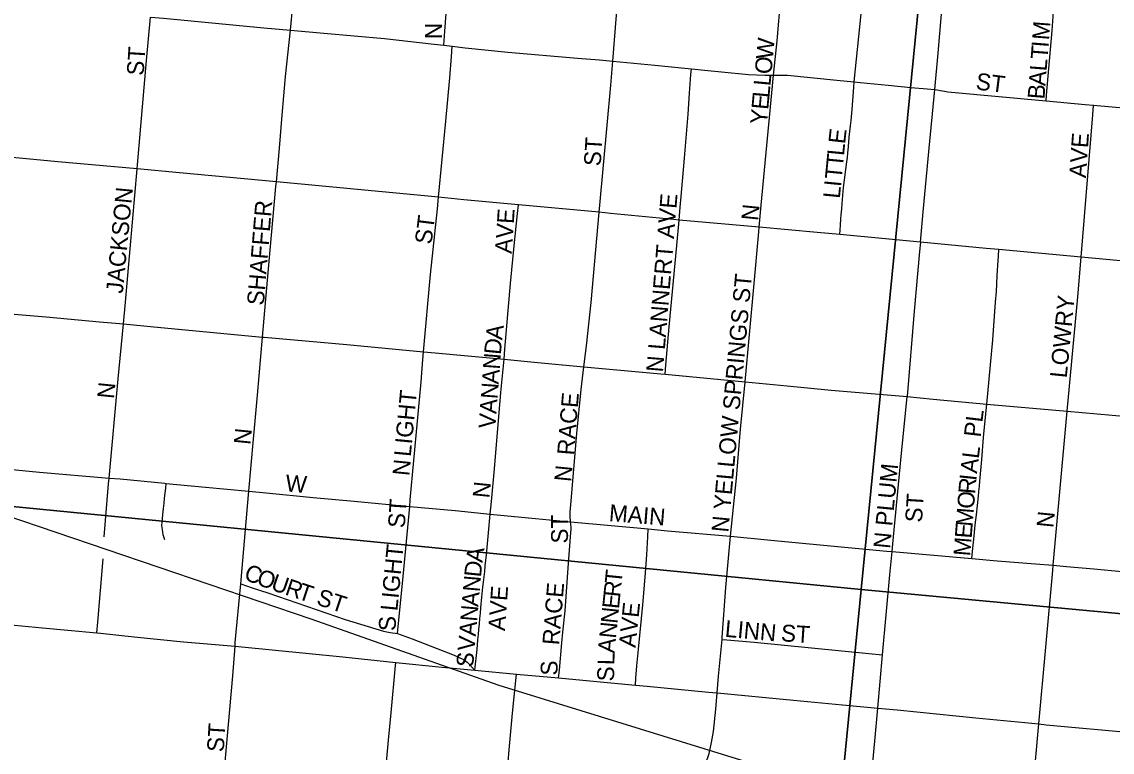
# Model space of a CAD drawing. Extents: x 1410790 to 1770854, y 566777 to 831614.
# Drawn here: x 1596372 to 1599605, y 703249 to 705415 of the extents above; entities that cross this region are included whole.
import ezdxf

# ---------------------------------------------------------------- set-up
doc = ezdxf.new("R2010")
doc.units = 0
for name, color, linetype in [('GM_X_City_Street', 7, 'Continuous'), ('GM_X_City_Street_Text', 7, 'Continuous'), ('GM_X_Rail_Line', 7, 'Continuous'), ('GM_X_Section', 7, 'Continuous'), ('GM_X_State_Route', 7, 'Continuous'), ('GM_X_US_Route', 7, 'Continuous')]:
    doc.layers.add(name, color=color, linetype=linetype)

msp = doc.modelspace()

# ---------------------------------------------------------------- linework, layer by layer
at = {"layer": 'GM_X_City_Street'}
for points in [[(1598840.1, 705236.8), (1598861, 705439.4), (1598863.5, 705471.4), (1598867.3, 705540.5), (1598872.1, 705604.7), (1598876, 705636.3), (1598878.7, 705664.4), (1598881, 705685.4), (1598881.8, 705699.3), (1598883.1, 705713.8), (1598883.9, 705728.3), (1598887.4, 705769.7), (1598888.7, 705785.2), (1598890.9, 705809.2)], [(1597168.5, 705390.7), (1597175.9, 705464.1), (1597191.7, 705627), (1597202.2, 705736.3)], [(1597623.6, 705345.8), (1597626.8, 705388), (1597647.5, 705663.5)], [(1598124, 705298.3), (1598134.4, 705423.1), (1598152.3, 705617.1)], [(1599409.2, 705180.5), (1599410.7, 705197.9), (1599417.4, 705277.1), (1599426.8, 705389.2), (1599431.3, 705445), (1599442.4, 705579.9), (1599445.7, 705614.4)], [(1598601.1, 705257), (1598611.3, 705359.2), (1598623, 705488.1), (1598631.2, 705571.8)], [(1596714.1, 704978.9), (1596715.1, 704991.2), (1596742.3, 705300.6), (1596753.5, 705429.3)], [(1596753.5, 705429.3), (1596792.1, 705425.8), (1597089.8, 705397.8), (1597168.5, 705390.7)], [(1597126.9, 704940.3), (1597135.7, 705040.9), (1597143.9, 705138.8), (1597154, 705252.7), (1597168.5, 705390.7)], [(1597168.5, 705390.7), (1597267.3, 705381.7), (1597447.5, 705365.9), (1597594.8, 705349.3), (1597623.6, 705345.8)], [(1597607.7, 704894.9), (1597628.9, 705120.2), (1597640.9, 705249.4), (1597645.7, 705312.7), (1597648.1, 705342.8)], [(1597623.6, 705345.8), (1597648.1, 705342.8)], [(1597648.1, 705342.8), (1597686.5, 705338.1), (1597812.9, 705325.3), (1598020.1, 705307.9), (1598085.1, 705302.1), (1598124, 705298.3)], [(1598084, 704850.4), (1598085.9, 704871.2), (1598118.1, 705227.6), (1598124, 705298.3)], [(1598124, 705298.3), (1598248.8, 705286.5), (1598357.4, 705275.4)], [(1598320.9, 704827.3), (1598324.1, 704865.1), (1598327.2, 704897.2), (1598336.7, 705010.4), (1598347.5, 705141), (1598351.7, 705203.5), (1598355.8, 705258.7), (1598357.4, 705275.4)], [(1598357.4, 705275.4), (1598396.1, 705271.5), (1598446.4, 705266.8), (1598527.1, 705259.5), (1598575.1, 705256.6), (1598601.1, 705257)], [(1598558.3, 704806), (1598564.5, 704871), (1598588.9, 705131.2), (1598601.1, 705257)], [(1598601.1, 705257), (1598626.2, 705257.4), (1598642.6, 705256.6), (1598789.1, 705242.1), (1598840.1, 705236.8)], [(1598797.2, 704784.5), (1598799.2, 704811.7), (1598800.6, 704830.8), (1598801.3, 704842.9), (1598803.2, 704860.8), (1598804.2, 704876.3), (1598808.8, 704923.8), (1598818.3, 704999.9), (1598820.1, 705012.9), (1598821.4, 705026.9), (1598823, 705044), (1598825.6, 705073.1), (1598827, 705090.2), (1598829.1, 705107.2), (1598831.2, 705122.1), (1598833.6, 705155.1), (1598838.9, 705221.1), (1598840.1, 705236.8)], [(1598840.1, 705236.8), (1598858.2, 705235.2), (1598940.8, 705227), (1599008.4, 705220.9), (1599056.3, 705216.6), (1599078.7, 705214.6)], [(1599078.7, 705214.6), (1599108, 705209.2), (1599117.6, 705207.7), (1599128.5, 705206.5), (1599409.2, 705180.5)], [(1599409.2, 705180.5), (1599524.7, 705169.8), (1599549.9, 705167.6)], [(1599512.8, 704717), (1599547.6, 705139.2), (1599549.9, 705167.6)], [(1599549.9, 705167.6), (1599704.4, 705154.1), (1599819.7, 705145), (1599846.7, 705142.8)], [(1596673.8, 704519), (1596679.8, 704584.1), (1596714.1, 704978.9)], [(1597086, 704480), (1597104, 704682.5), (1597125.7, 704927), (1597126.9, 704940.3)], [(1597563.5, 704436.9), (1597583.8, 704665.8), (1597604.5, 704860.9), (1597607.7, 704894.9)], [(1597801.8, 704414.4), (1597804.5, 704444.3), (1597820.9, 704638.7), (1597831.6, 704751.1), (1597841.7, 704846.4), (1597844.4, 704872.6)], [(1598038.8, 704392.3), (1598046.4, 704454.5), (1598060.3, 704582.9), (1598084, 704850.4)], [(1598279.7, 704370.1), (1598281.9, 704396.9), (1598287.4, 704464.6), (1598291.6, 704510.1), (1598313.9, 704751.9), (1598320.9, 704827.3)], [(1598516.6, 704347.3), (1598542.8, 704627.9), (1598557.1, 704792.4), (1598558.3, 704806)], [(1599233.2, 704281.6), (1599250.9, 704471.6), (1599259.1, 704583.4), (1599261.8, 704615.1), (1599264.3, 704662), (1599264.8, 704678.6), (1599265.6, 704692.8), (1599267.7, 704721.6), (1599269.1, 704739.7)], [(1599471.9, 704260.5), (1599503.2, 704599.4), (1599512.8, 704717)], [(1596630.9, 704062), (1596658.2, 704356.3), (1596673.8, 704519)], [(1597045.4, 704023.2), (1597059.5, 704177.5), (1597070.6, 704307.9), (1597086, 704480)], [(1597522.2, 703977.9), (1597524, 703997.8), (1597555.9, 704347.2), (1597561.5, 704413.3), (1597563.5, 704436.9)], [(1597760.9, 703955.2), (1597764.4, 703992.2), (1597773.7, 704089.4), (1597792.7, 704315.5), (1597801.8, 704414.4)], [(1597999, 703932.4), (1597997.9, 703949), (1597998, 703955.1), (1597998.2, 703961.6), (1598000.1, 703982.4), (1598018, 704194.4), (1598030.1, 704324.6), (1598038.8, 704392.3)], [(1598473.6, 703890.1), (1598490.7, 704061.4), (1598503.4, 704207.2), (1598516.6, 704347.3)], [(1598953, 703843.7), (1598955.1, 703867.1), (1598978.1, 704115.2), (1598997.3, 704303.6)], [(1599188.6, 703823.4), (1599190.7, 703844.2), (1599195.6, 703890.6), (1599198.8, 703923), (1599202.3, 703953.1), (1599208.2, 704008), (1599209.8, 704022.5), (1599211.5, 704037.6), (1599213, 704053.2), (1599218.3, 704117.3), (1599223.8, 704182.3), (1599231.3, 704262.3), (1599233.2, 704281.6)], [(1599430.2, 703803.4), (1599432.5, 703836.2), (1599471.9, 704260.5)], [(1596210.6, 704098.2), (1596312.7, 704090), (1596425, 704079.5), (1596630.9, 704062)], [(1596616.7, 703887.8), (1596629.4, 704044.9), (1596630.9, 704062)], [(1596630.9, 704062), (1596663.9, 704059.3), (1596796, 704046.7), (1596800.1, 704046.3)], [(1596796.7, 703878.4), (1596791.6, 703893.4), (1596788.8, 703909), (1596787.8, 703921), (1596789.1, 703940.8), (1596790.5, 703953.6), (1596792.6, 703971.4), (1596794, 703987.3), (1596795.7, 704001.9), (1596797.5, 704016.9), (1596798.8, 704032.5), (1596800.1, 704046.3)], [(1596800.1, 704046.3), (1596916.9, 704035.1), (1597045.4, 704023.2)], [(1597021.1, 703748.2), (1597030.4, 703851.6), (1597044.4, 704012.1), (1597045.4, 704023.2)], [(1597045.4, 704023.2), (1597096.5, 704018.3), (1597236, 704004.8), (1597357.9, 703993.2), (1597522.2, 703977.9)], [(1597486.5, 703600.7), (1597503.2, 703770), (1597522.2, 703977.9)], [(1597522.2, 703977.9), (1597657, 703965.3), (1597760.9, 703955.2)], [(1597715.5, 703492.1), (1597722, 703553.5), (1597724.7, 703581.8), (1597725.9, 703598.2), (1597727.4, 703613.1), (1597728.7, 703629.8), (1597730.2, 703645.3), (1597731.7, 703661.1), (1597732.9, 703676.9), (1597735.6, 703708.8), (1597739, 703738), (1597740.8, 703752.9), (1597742.5, 703769.3), (1597744.5, 703785.3), (1597746.4, 703801.5), (1597749.8, 703834.1), (1597755.8, 703899.6), (1597760.9, 703955.2)], [(1597760.9, 703955.2), (1597874.7, 703944.1), (1597957.4, 703936), (1597999, 703932.4)], [(1597963.8, 703469.4), (1597965.9, 703492.5), (1597973.3, 703572.8), (1597976.4, 703604.9), (1597982.8, 703668.4), (1597992.4, 703796), (1598000.3, 703900.7), (1598001, 703909.4), (1598000.6, 703916.1), (1597999, 703932.4)], [(1597999, 703932.4), (1598229.5, 703911.1)], [(1598191.3, 703448), (1598193, 703468.5), (1598196, 703505.4), (1598200.8, 703554), (1598213.8, 703686), (1598220.3, 703768), (1598225.1, 703834.4), (1598228.1, 703887.4), (1598229.5, 703911.1)], [(1598229.5, 703911.1), (1598286.9, 703905.7), (1598473.6, 703890.1)], [(1598448.4, 703583.4), (1598448.9, 703588.8), (1598459.3, 703737.1), (1598473.6, 703890.1)], [(1598473.6, 703890.1), (1598593, 703877.7), (1598936.4, 703845.1), (1598953, 703843.7)], [(1598924.3, 703538), (1598945.4, 703774.8), (1598953, 703843.7)], [(1598953, 703843.7), (1599188.6, 703823.4)], [(1596594.2, 703602.8), (1596597.2, 703634.1), (1596605.2, 703728.2), (1596613, 703822.5)], [(1599188.6, 703823.4), (1599263.5, 703816.9), (1599378.1, 703808), (1599430.2, 703803.4)], [(1599387.8, 703332.6), (1599428.9, 703788.3), (1599430.2, 703803.4)], [(1599430.2, 703803.4), (1599469.7, 703799.9), (1599550.6, 703792.8), (1599634.7, 703785.3), (1599865.4, 703763.4), (1599909.1, 703759.1)], [(1597004.4, 703563.1), (1597005.2, 703573.9), (1597021.1, 703748.2)], [(1597021.1, 703748.2), (1597055.1, 703736.8), (1597101.2, 703721.7), (1597330.6, 703642.9), (1597444.8, 703608.1), (1597464.6, 703604.2), (1597486.5, 703600.7)], [(1596170.1, 703643.6), (1596252.4, 703635.1), (1596350.8, 703625.8), (1596433.1, 703618), (1596508.7, 703610.9), (1596594.2, 703602.8)], [(1596594.2, 703602.8), (1596605.9, 703601.7), (1596705, 703591.1), (1596851.9, 703576.7), (1597004.4, 703563.1)], [(1597486.5, 703600.7), (1597529.2, 703585), (1597654.2, 703536.6), (1597666.6, 703531), (1597681.6, 703523.5), (1597692.9, 703515.8), (1597715.5, 703492.1)], [(1598434, 703424.9), (1598438.2, 703474.5), (1598448.4, 703583.4)], [(1598448.4, 703583.4), (1598462.6, 703582.2), (1598543.3, 703575), (1598883.8, 703542), (1598924.3, 703538)], [(1596924.6, 702672.4), (1596933.8, 702773.6), (1596948.9, 702936.9), (1596961.9, 703067.4), (1596976, 703230.8), (1596997.6, 703475.8), (1597004.4, 703563.1)], [(1597004.4, 703563.1), (1597014.9, 703562.3), (1597324.3, 703531.4), (1597481.3, 703515.2)], [(1598910.4, 703379.6), (1598924.3, 703538)], [(1597397, 702623.1), (1597401.2, 702670), (1597426.9, 702928.9), (1597432.1, 702992.8), (1597433.4, 703008.8), (1597439.4, 703073.6), (1597447.5, 703154.7), (1597459.4, 703284.4), (1597466.9, 703365.5), (1597480.4, 703506.1), (1597481.3, 703515.2)], [(1597481.3, 703515.2), (1597618.3, 703501), (1597715.5, 703492.1)], [(1597715.5, 703492.1), (1597839.2, 703480.8)], [(1597745.2, 702587.2), (1597748.3, 702598.6), (1597752.4, 702610.8), (1597755.9, 702619.6), (1597760.4, 702632.3), (1597763.4, 702647.8), (1597769.2, 702696.5), (1597772, 702729), (1597792.1, 702956.9), (1597797.4, 703022.2), (1597807.9, 703152.4), (1597817.7, 703266.9), (1597827.4, 703365), (1597837.3, 703461.5), (1597839.2, 703480.8)], [(1597839.2, 703480.8), (1597963.8, 703469.4)], [(1597963.8, 703469.4), (1597994.5, 703466.6), (1598191.3, 703448)], [(1598191.3, 703448), (1598226.6, 703444.6), (1598408, 703427.3), (1598434, 703424.9)], [(1598344.5, 703083.5), (1598348.7, 703092.5), (1598367.5, 703137.9), (1598399.2, 703213.7), (1598410, 703245.2), (1598417.5, 703277.7), (1598422.6, 703310.5), (1598429.9, 703376.1), (1598434, 703424.9)], [(1598434, 703424.9), (1598659.7, 703403.6), (1598805.5, 703389.8), (1598910.4, 703379.6)], [(1598877, 703034.8), (1598878, 703044.8), (1598891.5, 703174), (1598909.5, 703369), (1598910.4, 703379.6)], [(1598910.4, 703379.6), (1598967, 703374.3), (1599200.6, 703351.1), (1599387.8, 703332.6)], [(1599322.5, 702627.7), (1599334, 702747.6), (1599338.3, 702806.7), (1599340.5, 702824), (1599347.9, 702903), (1599350.9, 702935.6), (1599353.9, 702967), (1599355.2, 702983.3), (1599359.3, 703015.1), (1599387.8, 703332.6)], [(1599387.8, 703332.6), (1599409.7, 703330.2), (1599671.4, 703306.6), (1599769.3, 703296), (1599866.6, 703286.3)]]:
    msp.add_lwpolyline(points, dxfattribs=at)
at = {"layer": 'GM_X_Rail_Line'}
msp.add_lwpolyline([(1596169.6, 704004.7), (1597229.5, 703644.6), (1597786, 703448), (1598813.6, 703130), (1599029.2, 703066.1), (1599068.1, 703054.4), (1599162.7, 703027.9), (1599398.9, 702972), (1599444.3, 702961.3), (1599530.2, 702945.5), (1599602, 702931.7), (1599850, 702892)], dxfattribs=at)
at = {"layer": 'GM_X_Section'}
for points in [[(1594039.9, 709527.8), (1599376.7, 708982.6), (1598860.7, 703731.2), (1593585.4, 704247.5)], [(1599376.7, 708982.6), (1604648.8, 708516.3), (1604192.4, 703233.9), (1598860.7, 703731.2)], [(1593585.4, 704247.5), (1598860.7, 703731.2), (1598351.3, 698519.7), (1593108.3, 699057.6)], [(1598860.7, 703731.2), (1604192.4, 703233.9), (1603688.3, 697982.3), (1598351.3, 698519.7)]]:
    msp.add_lwpolyline(points, close=True, dxfattribs=at)
at = {"layer": 'GM_X_State_Route'}
for points in [[(1599036.5, 704761.7), (1599044.6, 704851.8), (1599064.5, 705061.5), (1599071.9, 705142.8), (1599078.7, 705214.6), (1599088.7, 705322), (1599107.8, 705544.7), (1599118.8, 705670.2), (1599128.7, 705788), (1599140.5, 705930), (1599154.1, 706075.3), (1599154.1, 706075.8)], [(1599036.5, 704761.7), (1599034, 704733.9), (1599018, 704556.9), (1598997.3, 704303.6)]]:
    msp.add_lwpolyline(points, dxfattribs=at)
at = {"layer": 'GM_X_US_Route'}
for points in [[(1599036.5, 704761.7), (1598797.2, 704784.5), (1598730.6, 704790.8), (1598558.3, 704806), (1598320.9, 704827.3), (1598304.8, 704828.7), (1598117.6, 704847.1), (1598084, 704850.4), (1597921.2, 704865.5), (1597844.4, 704872.6), (1597682.6, 704887.7), (1597607.7, 704894.9), (1597126.9, 704940.3), (1596840.1, 704967.2), (1596714.1, 704978.9), (1596479.3, 705000.2), (1596301.7, 705017)], [(1599989.9, 704672.8), (1599961, 704675.6), (1599829, 704687.5), (1599693.2, 704700.5), (1599512.8, 704717), (1599269.1, 704739.7), (1599231.1, 704743.2), (1599036.5, 704761.7)], [(1596257.6, 704556.7), (1596285.2, 704554.2), (1596338.1, 704549.5), (1596444.8, 704539.8), (1596602.9, 704525.5), (1596673.8, 704519), (1596763.9, 704510.9), (1597086, 704480), (1597090.5, 704479.5), (1597335.8, 704458.2), (1597563.5, 704436.9), (1597597.3, 704433.8), (1597801.8, 704414.4), (1597891.3, 704405.8), (1598038.8, 704392.3), (1598266.8, 704371.3), (1598279.7, 704370.1), (1598516.6, 704347.3)], [(1598516.6, 704347.3), (1598641.6, 704335.1), (1598771.8, 704322.5), (1598997.3, 704303.6)], [(1598997.3, 704303.6), (1599073.9, 704295.6), (1599233.2, 704281.6), (1599471.9, 704260.5), (1599782.6, 704233.1), (1599949, 704216.4)]]:
    msp.add_lwpolyline(points, dxfattribs=at)

# ---------------------------------------------------------------- texts
at = {"layer": 'GM_X_City_Street_Text'}
for s, rotation, p in [('M', 85.5756, (1599417.6, 705359.8)), ('N', 90, (1597617.5, 705363.9)), ('W', 84.7645, (1598598.7, 705302.3)), ('I', 85.5376, (1599415.8, 705337.8)), ('ST', 86.4254, (1596733.2, 705254.5)), ('T', 85.5699, (1599413.1, 705302.8)), ('O', 84.778, (1598594.7, 705258.5)), ('L', 85.5825, (1599410.4, 705267.7)), ('L', 84.7734, (1598591.5, 705223.4)), ('ST', 352.8783, (1599198.9, 705214.9)), ('A', 85.5594, (1599407, 705223.8)), ('L', 84.7821, (1598588.4, 705188.4)), ('B', 85.5752, (1599403.9, 705184.3)), ('E', 84.7734, (1598585.1, 705153.3)), ('Y', 84.7917, (1598581.2, 705109.5)), ('E', 83.6749, (1598813, 705051.5)), ('ST', 86.4254, (1598088.3, 704986.1)), ('AVE', 86.0569, (1599527.1, 704951)), ('T', 84.4893, (1598806.3, 704981.6)), ('L', 84.4988, (1598809.7, 705016.6)), ('T', 84.4716, (1598802.9, 704946.5)), ('I', 84.5088, (1598800.8, 704924.6)), ('JACKSON', 84.5592, (1596671.6, 704608)), ('N LANNERT AVE', 85.3217, (1598273.1, 704374.7)), ('L', 84.4716, (1598797.4, 704889.6)), ('SHAFFER', 85.3129, (1597089.5, 704572.7)), ('N', 84.2916, (1598554.8, 704823.7)), ('ST', 82.8783, (1597586.8, 704753.5)), ('E', 86.634, (1597830.8, 704815.2)), ('V', 85.8661, (1597827.5, 704770.6)), ('A', 85.8661, (1597824.4, 704726.7)), ('N YELLOW SPRINGS ST', 84.7383, (1598466.7, 703899.5)), ('LOWRY', 84.3993, (1599470, 704357.3)), ('A', 83.4715, (1597796.5, 704470.1)), ('D', 84.4395, (1597792.2, 704426.5)), ('N', 85.759, (1597789, 704383)), ('A', 85.7337, (1597785.7, 704339.1)), ('N', 84.2916, (1596645.2, 704295.7)), ('LIGHT', 84.5626, (1597525.2, 704124)), ('N', 85.7555, (1597782.5, 704295.2)), ('RACE', 85.361, (1598009.1, 704128.3)), ('A', 85.759, (1597779.2, 704251.3)), ('V', 85.7555, (1597776, 704207.4)), ('PL', 83.2931, (1599214.8, 704181.4)), ('N', 84.2937, (1597050, 704159.3)), ('L', 83.1529, (1599209.3, 704117.8)), ('A', 83.2301, (1599204.1, 704074.1)), ('N', 84.2937, (1597520.8, 704066.9)), ('N', 84.2916, (1598000.4, 704049.3)), ('N PLUM', 84.5067, (1598946.4, 703851.2)), ('W', 355.6039, (1597152.4, 704022.5)), ('R', 85.1617, (1599198.4, 704013.2)), ('I', 83.9109, (1599201.8, 704052.4)), ('N', 84.2916, (1597758.4, 704000.9)), ('O', 85.4923, (1599195, 703969.4)), ('ST', 86.1879, (1597507.5, 703912.6)), ('ST', 86.4118, (1599041, 703929.2)), ('MAIN', 355.3669, (1598111.7, 703934.5)), ('M', 85.4965, (1599190.8, 703916.8)), ('N', 84.2916, (1599430.4, 703912.9)), ('ST', 90, (1597991.5, 703867.9)), ('E', 85.5188, (1599188.1, 703881.7)), ('LIGHT', 84.5066, (1597485.5, 703666.2)), ('M', 85.4965, (1599184, 703829.1)), ('A', 81.6875, (1597737.7, 703809.6)), ('C', 338.7759, (1597027.6, 703762.3)), ('D', 84.0894, (1597733.3, 703766.4)), ('O', 339.1791, (1597064.8, 703747.9)), ('U', 341.1085, (1597107.7, 703731.6)), ('R', 341.5755, (1597149.7, 703717.2)), ('N', 85.0266, (1597729.5, 703722.8)), ('T', 84.1977, (1598150.1, 703746.8)), ('T', 341.5716, (1597187.3, 703704.7)), ('ST', 341.5738, (1597242.7, 703687.7)), ('AVE', 85.9188, (1597804.6, 703607.6)), ('RACE', 85.3685, (1597965.2, 703565.2)), ('R', 84.1855, (1598146.1, 703707.4)), ('A', 85.0147, (1597725.6, 703678.9)), ('E', 84.1977, (1598142.5, 703672.4)), ('N', 85.0094, (1597721.8, 703635.1)), ('N', 84.2029, (1598138.1, 703628.6)), ('AVE', 84.0895, (1598191.6, 703557.8)), ('S', 90, (1597481.1, 703608.3)), ('A', 85.0331, (1597718, 703591.2)), ('N', 84.1981, (1598133.6, 703584.8)), ('LINN', 354.8026, (1598455.2, 703591.3)), ('ST', 356.4262, (1598621.9, 703578.1)), ('V', 85.0266, (1597714.2, 703547.4)), ('A', 84.8135, (1598129.6, 703541.1)), ('S', 85.0208, (1597710, 703499.2)), ('L', 88.8012, (1598129, 703506.9)), ('S', 90, (1597960.7, 703476.3)), ('S', 88.7707, (1598127.9, 703458.5)), ('ST', 86.4262, (1596970.8, 703248.1))]:
    msp.add_text(s, height=50, rotation=rotation, dxfattribs=at).set_placement(p)

doc.saveas('drawing.dxf')
